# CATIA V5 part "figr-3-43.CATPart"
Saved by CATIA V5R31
Part number: Part1
Bounding box of the stored display mesh (mm): x 0 to 0, y -151.508 to 68.716, z -53.883 to 66.715
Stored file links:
  D:\PROJECTS\Project 2021\US EDITION\CATIA V5 6R 2021\Resources\Part Files\c03_catia_v5_6r2021_prt\figr-3-43.CATPart
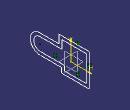
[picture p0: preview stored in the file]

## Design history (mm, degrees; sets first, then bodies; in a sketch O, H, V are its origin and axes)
Body1 (main body)
  Sketch1 on yz-plane, origin (0, 0, 0), H (0, 1, 0), V (0, 0, 1)
    point P1 (-23.9446, -41.7966)
    line L1 (-23.9446, -41.7966) -> (-23.9446, -23.995)
    line L2 (-23.9446, -23.995) -> (-115.8106, -23.995)
    arc A1 centre (-115.8106, -0.3669) radius 23.6281 from (-115.8106, -23.995) to (-115.8106, 23.2613) cw
    line L3 (-115.8106, 23.2613) -> (-33.6641, 23.2613)
    line L4 (-33.6641, 23.2613) -> (-33.6641, 54.6279)
    line L5 (-33.6641, 54.6279) -> (56.6292, 54.6279)
    line L6 (56.6292, 54.6279) -> (56.6292, -41.7966)
    line L7 (56.6292, -41.7966) -> (-23.9446, -41.7966)
    point P10 (-23.9446, -41.7966)
    line L8 (68.7159, 66.7146) -> (68.7159, -53.8833)
    line L9 (68.7159, -53.8833) -> (-36.0313, -53.8833)
    line L10 (-36.0313, -53.8833) -> (-36.0313, -36.0817)
    line L11 (-36.0313, -36.0817) -> (-115.8105, -36.0817)
    arc A2 centre (-115.8106, -0.3669) radius 35.7148 from (-115.8105, 35.348) to (-115.8105, -36.0817) ccw
    line L12 (-115.8105, 35.348) -> (-45.7508, 35.348)
    line L13 (-45.7508, 35.348) -> (-45.7508, 66.7146)
    line L14 (-45.7508, 66.7146) -> (68.7159, 66.7146)
    curve C1
    vertical: L1 V, L4 V, L6 V
    horizontal: L2 H, L5 H, L7 H
    tangency: A1 L2, L3 A1
    coincidence: P10 L1, P1 P10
